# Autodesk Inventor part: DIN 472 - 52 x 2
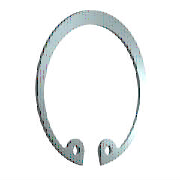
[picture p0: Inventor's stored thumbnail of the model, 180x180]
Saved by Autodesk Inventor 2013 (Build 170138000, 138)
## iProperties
Created: 2012-02
Part Number: DIN 472 - 52 x 2
Material: Stahl, weich
Description: Sicherungsring
Document SubType Name: Modeling
Standard: DIN 472
Designer: Dan
Standards Organization: DIN
Language: de-DE
Size Designation: 52 x 2
Categories: <MemberInstance><Categories><Category DisplayName="Wellenteile" InternalName="7f7aeb1f-a693-4053-b835-cee3144e0d98" Mnemonic="SHFT"><Category DisplayName="Siche
Density: 1 g/cm^3
IsCustomPart: 0
Author: Dan
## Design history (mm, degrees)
sketch "Skizze1"
  geometry: L1 (0, 15.113)-(0, -73.177) reference; L2 (-45.5, 0)-(45.5, 0) reference; L3 (-4.964, 2.5)-(1.502, 2.5); L4 (0, -2.2)-(-5.307, -2.2); L5 (0, -25)-(-11.662, -49.905); L6 (-11.662, -49.905)-(-25.145, -43.591); L7 (-10.242, -46.871)-(-20.725, -41.962); L8 (-7.978, -47.931)-(-9.35, -50.862); L9 (7.978, -47.931)-(9.35, -50.862); C1 r 1.25 at (-10.242, -46.871); C2 r 1.25 at (10.242, -46.871); A1 r 23.975 centre (0, -26.175) between (14.933, -44.931) and (-14.933, -44.931); A2 r 27.5 centre (0, -25) between (9.35, -50.862) and (-9.35, -50.862); A3 r 2.5 centre (-10.242, -46.871) between (-7.978, -47.931) and (-11.809, -44.923); A4 r 2.5 centre (-13.376, -42.975) between (-14.933, -44.931) and (-11.809, -44.923); A5 r 2.5 centre (13.376, -42.975) between (11.809, -44.923) and (14.933, -44.931); A6 r 2.5 centre (10.242, -46.871) between (11.809, -44.923) and (7.978, -47.931); 3 further points
  constraints: 15 point on circle, 14 end point, 9 symmetric about line, 8 centre point, 6 tangent, 4 coincident, 4 point on line, 3 perpendicular, 1 parallel, 4 other
  dimensions: "d8" = 1.175 distance of A1.centre L5.start (= 0.25 x SRB1); "d38" = 4.7 distance between parallel lines of L4 L3 (= SRB1); "d39" = 25 distance from line of L5.start L2 (= 0.5 x WD); "d43" = 27.5 radius of A2 (= 0.5 x ND); "d45" = 3.35 distance between parallel lines of L7 L6 (= 0.5 x SRB2); "d46" = 2.5 radius of A4 (= SD5); "d47" = 9.35 distance from line of L1 L8.end (= 0.17 x ND); "d48" = 2.5 diameter of C1 (= SD5); "d49" = 2.5 radius of A3 (= SD5)
extrude "Körper" new body sketch "Skizze1" distance "d2" = 2 (= SD); taper "d3" = 0 deg
workaxis "Work Axis1"
workaxis "Work Axis2"
workplane "Work Plane1"
body "Solid1"
other parameters: "SD" = 2 [user parameter; used in 1 equation term], "SRB1" = 4.7 [user parameter; used in 2 equation terms], "ND" = 55 [user parameter; used in 2 equation terms], "SRB2" = 6.7 [user parameter; used in 1 equation term], "SD5" = 2.5 [user parameter; used in 3 equation terms], "d50" = 0, "d51" = 0, "d52" = 0, "d53" = 0, "SD6" = 56.2 [user parameter], "NND" = 52 [user parameter; used in 1 equation term], "WDMAX" = 52 (= NND) [user parameter]
